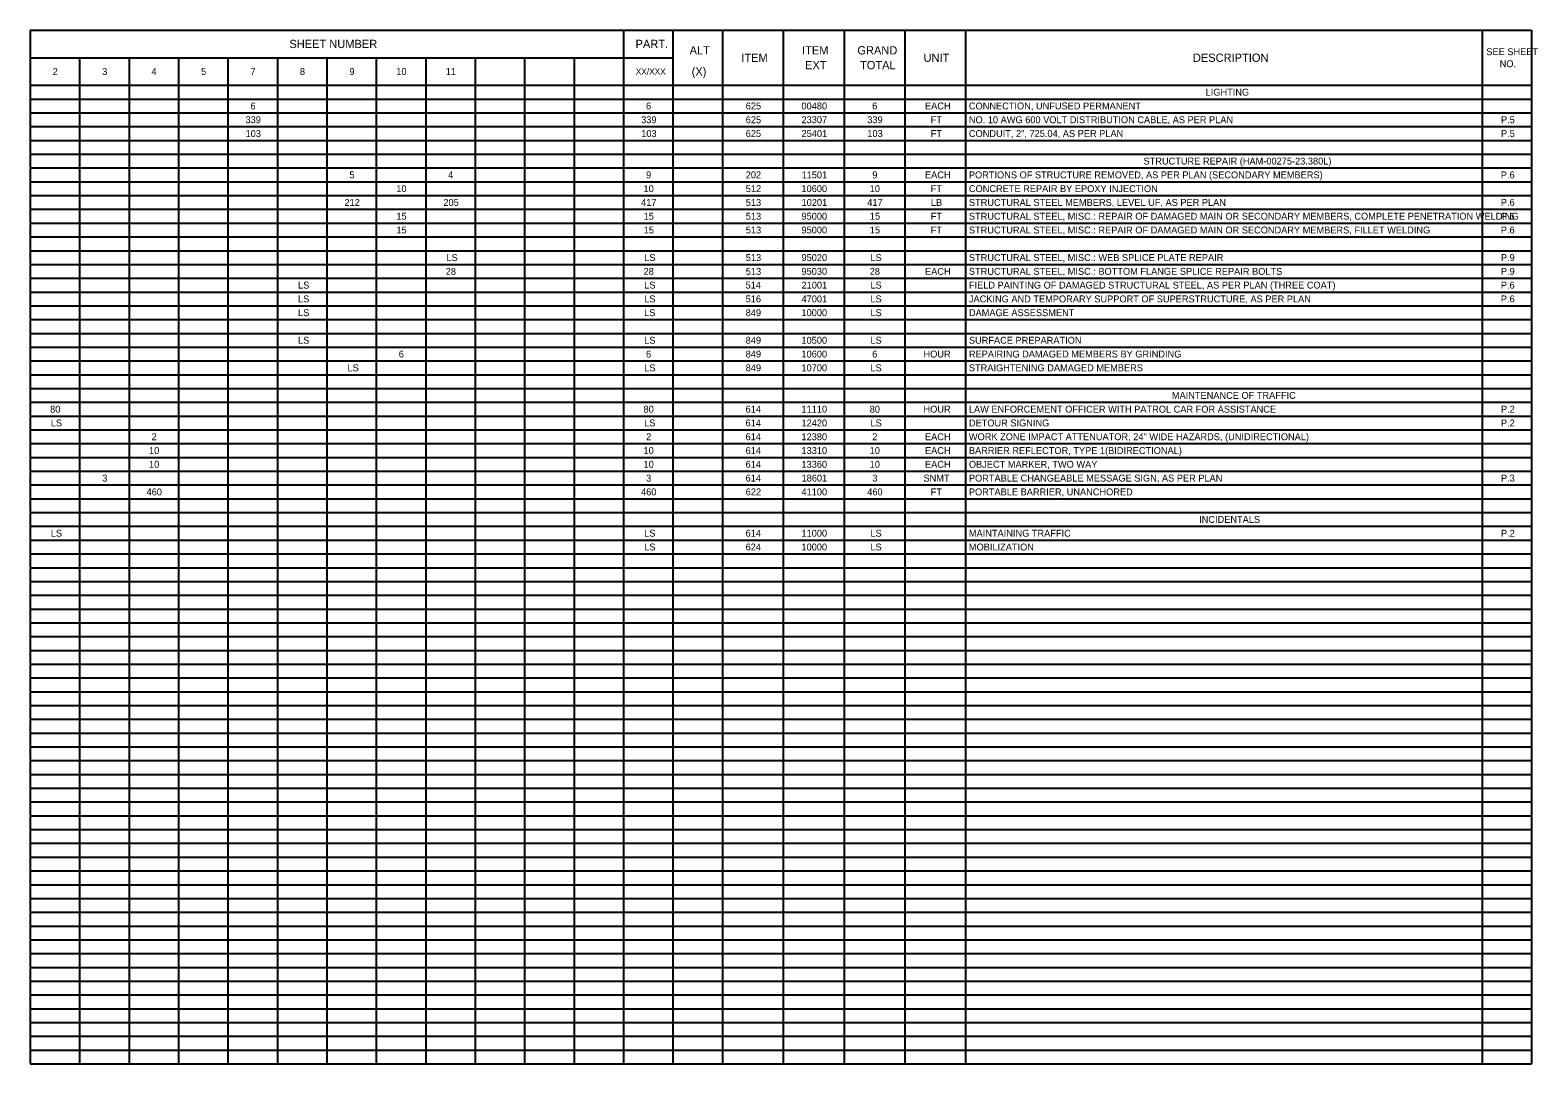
# Model space of a CAD drawing. Extents: x -38.5 to 34, y 0 to 22.
# Drawn here: x -38.5 to -7.87, y 0.5 to 21.5 of the extents above; entities that cross this region are included whole.
import ezdxf

# ---------------------------------------------------------------- set-up
doc = ezdxf.new("R2010")
doc.units = 0
doc.layers.add('Default', color=7, linetype='Continuous')

msp = doc.modelspace()

# ---------------------------------------------------------------- linework, layer by layer
at = {"layer": 'Default'}
for p, q in [((-38.5, 21.5), (-7.996, 21.5)), ((-38.5, 21.5), (-38.5, 0.5)), ((-26.444, 21.5), (-26.444, 0.5)), ((-25.439, 21.5), (-25.439, 0.5)), ((-24.434, 21.5), (-24.434, 0.5)), ((-23.199, 21.5), (-23.199, 0.5)), ((-21.964, 21.5), (-21.964, 0.5)), ((-20.728, 21.5), (-20.728, 0.5)), ((-19.493, 21.5), (-19.493, 0.5)), ((-9.001, 21.5), (-9.001, 0.5)), ((-7.996, 21.5), (-7.996, 0.5)), ((-38.5, 20.94), (-25.439, 20.94)), ((-37.495, 20.94), (-37.495, 0.5)), ((-36.491, 20.94), (-36.491, 0.5)), ((-35.486, 20.94), (-35.486, 0.5)), ((-34.481, 20.94), (-34.481, 0.5)), ((-33.476, 20.94), (-33.476, 0.5)), ((-32.472, 20.94), (-32.472, 0.5)), ((-31.467, 20.94), (-31.467, 0.5)), ((-30.462, 20.94), (-30.462, 0.5)), ((-29.458, 20.94), (-29.458, 0.5)), ((-28.453, 20.94), (-28.453, 0.5)), ((-27.448, 20.94), (-27.448, 0.5)), ((-38.5, 20.38), (-7.996, 20.38)), ((-38.5, 20.1), (-7.996, 20.1)), ((-38.5, 19.82), (-7.996, 19.82)), ((-38.5, 19.54), (-7.996, 19.54)), ((-38.5, 19.26), (-7.996, 19.26)), ((-38.5, 18.98), (-7.996, 18.98)), ((-38.5, 18.7), (-7.996, 18.7)), ((-38.5, 18.42), (-7.996, 18.42)), ((-38.5, 18.14), (-7.996, 18.14)), ((-38.5, 17.86), (-7.996, 17.86)), ((-38.5, 17.58), (-7.996, 17.58)), ((-38.5, 17.3), (-7.996, 17.3)), ((-38.5, 17.02), (-7.996, 17.02)), ((-38.5, 16.74), (-7.996, 16.74)), ((-38.5, 16.46), (-7.996, 16.46)), ((-38.5, 16.18), (-7.996, 16.18)), ((-38.5, 15.9), (-7.996, 15.9)), ((-38.5, 15.62), (-7.996, 15.62)), ((-38.5, 15.34), (-7.996, 15.34)), ((-38.5, 15.06), (-7.996, 15.06)), ((-38.5, 14.78), (-7.996, 14.78)), ((-38.5, 14.5), (-7.996, 14.5)), ((-38.5, 14.22), (-7.996, 14.22)), ((-38.5, 13.94), (-7.996, 13.94)), ((-38.5, 13.66), (-7.996, 13.66)), ((-38.5, 13.38), (-7.996, 13.38)), ((-38.5, 13.1), (-7.996, 13.1)), ((-38.5, 12.82), (-7.996, 12.82)), ((-38.5, 12.54), (-7.996, 12.54)), ((-38.5, 12.26), (-7.996, 12.26)), ((-38.5, 11.98), (-7.996, 11.98)), ((-38.5, 11.7), (-7.996, 11.7)), ((-38.5, 11.42), (-7.996, 11.42)), ((-38.5, 11.14), (-7.996, 11.14)), ((-38.5, 10.86), (-7.996, 10.86)), ((-38.5, 10.58), (-7.996, 10.58)), ((-38.5, 10.3), (-7.996, 10.3)), ((-38.5, 10.02), (-7.996, 10.02)), ((-38.5, 9.74), (-7.996, 9.74)), ((-38.5, 9.46), (-7.996, 9.46)), ((-38.5, 9.18), (-7.996, 9.18)), ((-38.5, 8.9), (-7.996, 8.9)), ((-38.5, 8.62), (-7.996, 8.62)), ((-38.5, 8.34), (-7.996, 8.34)), ((-38.5, 8.06), (-7.996, 8.06)), ((-38.5, 7.78), (-7.996, 7.78)), ((-38.5, 7.5), (-7.996, 7.5)), ((-38.5, 7.22), (-7.996, 7.22)), ((-38.5, 6.94), (-7.996, 6.94)), ((-38.5, 6.66), (-7.996, 6.66)), ((-38.5, 6.38), (-7.996, 6.38)), ((-38.5, 6.1), (-7.996, 6.1)), ((-38.5, 5.82), (-7.996, 5.82)), ((-38.5, 5.54), (-7.996, 5.54)), ((-38.5, 5.26), (-7.996, 5.26)), ((-38.5, 4.98), (-7.996, 4.98)), ((-38.5, 4.7), (-7.996, 4.7)), ((-38.5, 4.42), (-7.996, 4.42)), ((-38.5, 4.14), (-7.996, 4.14)), ((-38.5, 3.86), (-7.996, 3.86)), ((-38.5, 3.58), (-7.996, 3.58)), ((-38.5, 3.3), (-7.996, 3.3)), ((-38.5, 3.02), (-7.996, 3.02)), ((-38.5, 2.74), (-7.996, 2.74)), ((-38.5, 2.46), (-7.996, 2.46)), ((-38.5, 2.18), (-7.996, 2.18)), ((-38.5, 1.9), (-7.996, 1.9)), ((-38.5, 1.62), (-7.996, 1.62)), ((-38.5, 1.34), (-7.996, 1.34)), ((-38.5, 1.06), (-7.996, 1.06)), ((-38.5, 0.78), (-7.996, 0.78)), ((-38.5, 0.5), (-7.996, 0.5))]:
    msp.add_line(p, q, dxfattribs=at)

# ---------------------------------------------------------------- texts
for s, height, p in [('SHEET NUMBER', 0.168, (-33.233, 21.136)), ('PART.', 0.168, (-26.199, 21.136)), ('ALT', 0.168, (-25.101, 21.006)), ('ITEM', 0.168, (-22.816, 21.006)), ('GRAND', 0.168, (-21.693, 21.006)), ('ITEM', 0.168, (-24.051, 20.856)), ('EXT', 0.168, (-22.756, 20.706)), ('TOTAL', 0.168, (-21.639, 20.706)), ('UNIT', 0.168, (-20.348, 20.856)), ('DESCRIPTION', 0.168, (-14.876, 20.856)), ('SEE SHEET ', 0.14, (-8.914, 20.992)), ('NO.', 0.14, (-8.643, 20.747)), ('2', 0.14, (-38.042, 20.59)), ('3', 0.14, (-37.036, 20.59)), ('4', 0.14, (-36.035, 20.59)), ('5', 0.14, (-35.027, 20.59)), ('7', 0.14, (-34.024, 20.59)), ('8', 0.14, (-33.02, 20.59)), ('9', 0.14, (-32.014, 20.59)), ('10', 0.14, (-31.061, 20.59)), ('11', 0.14, (-30.055, 20.59)), ('XX/XXX', 0.126, (-26.195, 20.597)), ('(X)', 0.168, (-25.059, 20.576)), ('LIGHTING', 0.14, (-14.617, 20.17)), ('6', 0.14, (-34.025, 19.89)), ('6', 0.14, (-25.987, 19.89)), ('625', 0.14, (-23.961, 19.89)), ('00480', 0.14, (-22.829, 19.89)), ('6', 0.14, (-21.392, 19.89)), ('EACH', 0.14, (-20.319, 19.89)), ('CONNECTION, UNFUSED PERMANENT', 0.14, (-19.427, 19.89)), ('339', 0.14, (-34.124, 19.61)), ('339', 0.14, (-26.086, 19.61)), ('625', 0.14, (-23.961, 19.61)), ('23307', 0.14, (-22.828, 19.61)), ('339', 0.14, (-21.491, 19.61)), ('FT', 0.14, (-20.203, 19.61)), ('NO. 10 AWG 600 VOLT DISTRIBUTION CABLE, AS PER PLAN', 0.14, (-19.427, 19.61)), ('P.5', 0.14, (-8.617, 19.61)), ('103', 0.14, (-34.123, 19.33)), ('103', 0.14, (-26.085, 19.33)), ('625', 0.14, (-23.961, 19.33)), ('25401', 0.14, (-22.827, 19.33)), ('103', 0.14, (-21.49, 19.33)), ('FT', 0.14, (-20.203, 19.33)), ('CONDUIT, 2", 725.04, AS PER PLAN', 0.14, (-19.427, 19.33)), ('P.5', 0.14, (-8.617, 19.33)), ('STRUCTURE REPAIR (HAM-00275-23.380L)', 0.14, (-15.879, 18.77)), ('5', 0.14, (-32.013, 18.49)), ('4', 0.14, (-30.007, 18.49)), ('9', 0.14, (-25.986, 18.49)), ('202', 0.14, (-23.961, 18.49)), ('11501', 0.14, (-22.827, 18.49)), ('9', 0.14, (-21.39, 18.49)), ('EACH', 0.14, (-20.319, 18.49)), ('PORTIONS OF STRUCTURE REMOVED, AS PER PLAN (SECONDARY MEMBERS)', 0.14, (-19.427, 18.49)), ('P.6', 0.14, (-8.619, 18.49)), ('10', 0.14, (-31.061, 18.21)), ('10', 0.14, (-26.038, 18.21)), ('512', 0.14, (-23.961, 18.21)), ('10600', 0.14, (-22.829, 18.21)), ('10', 0.14, (-21.443, 18.21)), ('FT', 0.14, (-20.203, 18.21)), ('CONCRETE REPAIR BY EPOXY INJECTION', 0.14, (-19.427, 18.21)), ('212', 0.14, (-32.114, 17.93)), ('15', 0.14, (-31.059, 17.65)), ('205', 0.14, (-30.104, 17.93)), ('417', 0.14, (-26.087, 17.93)), ('15', 0.14, (-26.035, 17.65)), ('513', 0.14, (-23.96, 17.93)), ('513', 0.14, (-23.96, 17.65)), ('95000', 0.14, (-22.829, 17.65)), ('10201', 0.14, (-22.827, 17.93)), ('417', 0.14, (-21.492, 17.93)), ('15', 0.14, (-21.44, 17.65)), ('FT', 0.14, (-20.203, 17.65)), ('LB', 0.14, (-20.2, 17.93)), ('STRUCTURAL STEEL MEMBERS, LEVEL UF, AS PER PLAN', 0.14, (-19.427, 17.93)), ('STRUCTURAL STEEL, MISC.: REPAIR OF DAMAGED MAIN OR SECONDARY MEMBERS, COMPLETE PENETRATION WELDING', 0.14, (-19.427, 17.65)), ('P.6', 0.14, (-8.619, 17.93)), ('P.6', 0.14, (-8.619, 17.65)), ('15', 0.14, (-31.059, 17.37)), ('15', 0.14, (-26.035, 17.37)), ('513', 0.14, (-23.96, 17.37)), ('95000', 0.14, (-22.829, 17.37)), ('15', 0.14, (-21.44, 17.37)), ('FT', 0.14, (-20.203, 17.37)), ('STRUCTURAL STEEL, MISC.: REPAIR OF DAMAGED MAIN OR SECONDARY MEMBERS, FILLET WELDING', 0.14, (-19.427, 17.37)), ('P.6', 0.14, (-8.619, 17.37)), ('LS', 0.14, (-30.042, 16.81)), ('LS', 0.14, (-26.024, 16.81)), ('513', 0.14, (-23.96, 16.81)), ('95020', 0.14, (-22.829, 16.81)), ('LS', 0.14, (-21.428, 16.81)), ('STRUCTURAL STEEL, MISC.: WEB SPLICE PLATE REPAIR', 0.14, (-19.427, 16.81)), ('P.9', 0.14, (-8.618, 16.81)), ('28', 0.14, (-30.056, 16.53)), ('28', 0.14, (-26.037, 16.53)), ('513', 0.14, (-23.96, 16.53)), ('95030', 0.14, (-22.829, 16.53)), ('28', 0.14, (-21.442, 16.53)), ('EACH', 0.14, (-20.319, 16.53)), ('STRUCTURAL STEEL, MISC.: BOTTOM FLANGE SPLICE REPAIR BOLTS', 0.14, (-19.427, 16.53)), ('P.9', 0.14, (-8.618, 16.53)), ('LS', 0.14, (-33.057, 16.25)), ('LS', 0.14, (-26.024, 16.25)), ('514', 0.14, (-23.964, 16.25)), ('21001', 0.14, (-22.827, 16.25)), ('LS', 0.14, (-21.428, 16.25)), ('FIELD PAINTING OF DAMAGED STRUCTURAL STEEL, AS PER PLAN (THREE COAT)', 0.14, (-19.427, 16.25)), ('P.6', 0.14, (-8.619, 16.25)), ('LS', 0.14, (-33.057, 15.97)), ('LS', 0.14, (-26.024, 15.97)), ('516', 0.14, (-23.963, 15.97)), ('47001', 0.14, (-22.827, 15.97)), ('LS', 0.14, (-21.428, 15.97)), ('JACKING AND TEMPORARY SUPPORT OF SUPERSTRUCTURE, AS PER PLAN', 0.14, (-19.427, 15.97)), ('P.6', 0.14, (-8.619, 15.97)), ('LS', 0.14, (-33.057, 15.69)), ('LS', 0.14, (-26.024, 15.69)), ('849', 0.14, (-23.962, 15.69)), ('10000', 0.14, (-22.829, 15.69)), ('LS', 0.14, (-21.428, 15.69)), ('DAMAGE ASSESSMENT', 0.14, (-19.427, 15.69)), ('LS', 0.14, (-33.057, 15.13)), ('LS', 0.14, (-26.024, 15.13)), ('849', 0.14, (-23.962, 15.13)), ('10500', 0.14, (-22.829, 15.13)), ('LS', 0.14, (-21.428, 15.13)), ('SURFACE PREPARATION', 0.14, (-19.427, 15.13)), ('LS', 0.14, (-32.052, 14.57)), ('6', 0.14, (-31.011, 14.85)), ('LS', 0.14, (-26.024, 14.57)), ('6', 0.14, (-25.987, 14.85)), ('849', 0.14, (-23.962, 14.85)), ('849', 0.14, (-23.962, 14.57)), ('10600', 0.14, (-22.829, 14.85)), ('10700', 0.14, (-22.829, 14.57)), ('LS', 0.14, (-21.428, 14.57)), ('6', 0.14, (-21.392, 14.85)), ('HOUR', 0.14, (-20.349, 14.85)), ('STRAIGHTENING DAMAGED MEMBERS', 0.14, (-19.427, 14.57)), ('REPAIRING DAMAGED MEMBERS BY GRINDING', 0.14, (-19.427, 14.85)), ('MAINTENANCE OF TRAFFIC', 0.14, (-15.303, 14.01)), ('80', 0.14, (-38.094, 13.73)), ('80', 0.14, (-26.038, 13.73)), ('614', 0.14, (-23.964, 13.73)), ('11110', 0.14, (-22.829, 13.73)), ('80', 0.14, (-21.443, 13.73)), ('HOUR', 0.14, (-20.349, 13.73)), ('LAW ENFORCEMENT OFFICER WITH PATROL CAR FOR ASSISTANCE', 0.14, (-19.427, 13.73)), ('P.2', 0.14, (-8.617, 13.73)), ('LS', 0.14, (-38.08, 13.45)), ('LS', 0.14, (-26.024, 13.45)), ('614', 0.14, (-23.964, 13.45)), ('12420', 0.14, (-22.829, 13.45)), ('LS', 0.14, (-21.428, 13.45)), ('DETOUR SIGNING', 0.14, (-19.427, 13.45)), ('P.2', 0.14, (-8.617, 13.45)), ('2', 0.14, (-36.032, 13.17)), ('2', 0.14, (-25.985, 13.17)), ('614', 0.14, (-23.964, 13.17)), ('12380', 0.14, (-22.829, 13.17)), ('2', 0.14, (-21.39, 13.17)), ('EACH', 0.14, (-20.319, 13.17)), ('WORK ZONE IMPACT ATTENUATOR, 24" WIDE HAZARDS, (UNIDIRECTIONAL)', 0.14, (-19.427, 13.17)), ('10', 0.14, (-36.085, 12.89)), ('10', 0.14, (-26.038, 12.89)), ('614', 0.14, (-23.964, 12.89)), ('13310', 0.14, (-22.829, 12.89)), ('10', 0.14, (-21.443, 12.89)), ('EACH', 0.14, (-20.319, 12.89)), ('BARRIER REFLECTOR, TYPE 1(BIDIRECTIONAL)', 0.14, (-19.427, 12.89)), ('10', 0.14, (-36.085, 12.61)), ('10', 0.14, (-26.038, 12.61)), ('614', 0.14, (-23.964, 12.61)), ('13360', 0.14, (-22.829, 12.61)), ('10', 0.14, (-21.443, 12.61)), ('EACH', 0.14, (-20.319, 12.61)), ('OBJECT MARKER, TWO WAY', 0.14, (-19.427, 12.61)), ('3', 0.14, (-37.036, 12.33)), ('3', 0.14, (-25.985, 12.33)), ('614', 0.14, (-23.964, 12.33)), ('18601', 0.14, (-22.827, 12.33)), ('3', 0.14, (-21.389, 12.33)), ('SNMT', 0.14, (-20.35, 12.33)), ('PORTABLE CHANGEABLE MESSAGE SIGN, AS PER PLAN', 0.14, (-19.427, 12.33)), ('P.3', 0.14, (-8.617, 12.33)), ('460', 0.14, (-36.135, 12.05)), ('460', 0.14, (-26.088, 12.05)), ('622', 0.14, (-23.961, 12.05)), ('41100', 0.14, (-22.829, 12.05)), ('460', 0.14, (-21.493, 12.05)), ('FT', 0.14, (-20.203, 12.05)), ('PORTABLE BARRIER, UNANCHORED', 0.14, (-19.427, 12.05)), ('LS', 0.14, (-38.08, 11.21)), ('LS', 0.14, (-26.024, 11.21)), ('614', 0.14, (-23.964, 11.21)), ('11000', 0.14, (-22.829, 11.21)), ('LS', 0.14, (-21.428, 11.21)), ('MAINTAINING TRAFFIC', 0.14, (-19.427, 11.21)), ('INCIDENTALS', 0.14, (-14.749, 11.49)), ('P.2', 0.14, (-8.617, 11.21)), ('LS', 0.14, (-26.024, 10.93)), ('624', 0.14, (-23.964, 10.93)), ('10000', 0.14, (-22.829, 10.93)), ('LS', 0.14, (-21.428, 10.93)), ('MOBILIZATION', 0.14, (-19.427, 10.93))]:
    msp.add_text(s, height=height, dxfattribs=at).set_placement(p)

doc.saveas('drawing.dxf')
